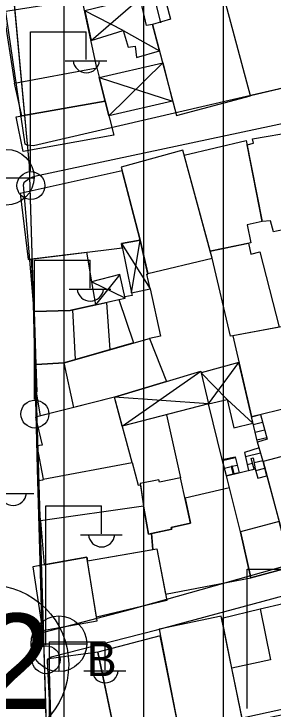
# Model space of a CAD drawing. Extents: x 417997 to 421451, y 4451742 to 4455216.
# Drawn here: x 419575.4 to 419608, y 4452787 to 4452874.4 of the extents above; entities that cross this region are included whole.
import ezdxf

# ---------------------------------------------------------------- set-up
doc = ezdxf.new("R2010")
doc.units = 0
for name, color, linetype in [('ADAKENARI', 7, 'Continuous'), ('B_Merdiven', 7, 'Continuous'), ('B_Mesken', 7, 'Continuous'), ('B_Sundurma', 7, 'Continuous'), ('B_Teras', 7, 'Continuous'), ('KD_DAIRE', 7, 'Continuous'), ('KD_YGEN', 7, 'Continuous'), ('PL_KON_MEV_350', 7, 'Continuous'), ('S_Elektrik_Diregi', 7, 'Continuous'), ('S_Rogar_Kapagi', 7, 'Continuous'), ('S_Rogar_Kapagi_Buski', 7, 'Continuous'), ('Sinir_Duvar_tek_tarafa_ait', 7, 'Continuous'), ('TR_ORTAYOGUNKONUT', 7, 'Continuous'), ('Yol_Sose', 7, 'Continuous')]:
    doc.layers.add(name, color=color, linetype=linetype)

msp = doc.modelspace()

# ---------------------------------------------------------------- linework, layer by layer
at = {"layer": 'ADAKENARI'}
for p, q in [((419577.387, 4452855.396), (419570.344, 4452931.114)), ((419577.387, 4452855.396), (419570.344, 4452931.114)), ((419580.562, 4452749.662), (419577.387, 4452855.396)), ((419580.562, 4452749.662), (419577.387, 4452855.396))]:
    msp.add_line(p, q, dxfattribs=at)
at = {"layer": 'B_Merdiven'}
for p, q in [((419605.259, 4452823.799), (419606.393, 4452824.078)), ((419605.49, 4452822.826), (419606.654, 4452823.113)), ((419605.72, 4452821.853), (419606.914, 4452822.147)), ((419605.95, 4452820.88), (419607.175, 4452821.181)), ((419604.497, 4452818.778), (419606.4, 4452819.269)), ((419601.631, 4452818.304), (419603.22, 4452818.69)), ((419604.723, 4452817.803), (419605.384, 4452817.974)), ((419605.599, 4452818.029), (419606.678, 4452818.308)), ((419601.877, 4452817.334), (419602.701, 4452817.535)), ((419602.84, 4452817.568), (419603.476, 4452817.723)), ((419605.795, 4452817.047), (419606.94, 4452817.343))]:
    msp.add_line(p, q, dxfattribs=at)
for points in [[(419606.391, 4452824.088), (419607.227, 4452820.991), (419606.016, 4452820.602), (419605.257, 4452823.808)], [(419607.199, 4452816.377), (419606.725, 4452818.149), (419606.218, 4452819.897), (419604.376, 4452819.299), (419604.899, 4452817.039), (419605.596, 4452817.209), (419605.223, 4452818.55), (419605.495, 4452818.609), (419605.74, 4452817.244), (419606.067, 4452816.085)], [(419602.124, 4452816.365), (419601.603, 4452818.415), (419603.202, 4452818.757), (419603.733, 4452816.756), (419603.101, 4452816.603), (419602.833, 4452817.597), (419602.697, 4452817.552), (419602.958, 4452816.568)]]:
    msp.add_lwpolyline(points, close=True, dxfattribs=at)
at = {"layer": 'B_Mesken'}
for points in [[(419601.122, 4452879.173), (419610.231, 4452881.446), (419611.357, 4452877.326), (419613.838, 4452866.195), (419605.127, 4452864.146)], [(419594.183, 4452877.313), (419595.097, 4452873.79), (419592.855, 4452873.132), (419595.839, 4452861.659), (419605.127, 4452864.146), (419601.122, 4452879.173)], [(419574.14, 4452874.723), (419575.523, 4452865.729), (419585.859, 4452867.663), (419584.005, 4452876.294)], [(419576.409, 4452861.628), (419575.523, 4452865.729), (419585.859, 4452867.663), (419586.893, 4452863.481)], [(419575.71, 4452861.505), (419586.893, 4452863.481), (419587.978, 4452859.205), (419576.599, 4452857.154)], [(419604.708, 4452857.963), (419605.529, 4452858.181), (419605.412, 4452858.754), (419610.784, 4452859.653), (419611.671, 4452855.297), (419612.25, 4452852.46), (419612.932, 4452849.113), (419613.116, 4452848.103), (419608.414, 4452847.12), (419608.031, 4452847.024), (419607.67, 4452848.42), (419606.623, 4452848.348)], [(419596.828, 4452856.671), (419604.594, 4452858.534), (419606.623, 4452848.348), (419604.737, 4452847.921), (419605.206, 4452845.68), (419600.086, 4452844.601)], [(419588.902, 4452855.173), (419591.287, 4452845.979), (419592.244, 4452841.79), (419600.323, 4452843.723), (419596.653, 4452857.32)], [(419589.017, 4452854.73), (419576.206, 4452851.873), (419577.234, 4452843.585), (419589.04, 4452845.013), (419588.927, 4452845.567), (419591.287, 4452845.979)], [(419602.924, 4452833.961), (419602.652, 4452833.916), (419600.323, 4452843.723), (419600.086, 4452844.601), (419604.898, 4452845.615), (419605.206, 4452844.251), (419606.326, 4452844.539), (419608.736, 4452835.055)], [(419578, 4452837.03), (419577.65, 4452843.636), (419584.53, 4452844.468), (419585.174, 4452840.763), (419585.696, 4452837.867), (419582.825, 4452837.219), (419582.477, 4452837.14)], [(419578.219, 4452830.344), (419578, 4452837.03), (419582.477, 4452837.14), (419588.616, 4452838.526), (419590.441, 4452833.069), (419581.74, 4452830.577)], [(419602.924, 4452833.961), (419605.257, 4452823.808), (419610.099, 4452825.001), (419610.158, 4452824.534), (419613.16, 4452825.235), (419610.827, 4452835.448)], [(419578.785, 4452823.922), (419578.253, 4452826.901), (419578.358, 4452826.945), (419578.219, 4452830.344), (419581.74, 4452830.577), (419592.468, 4452833.649), (419594.603, 4452828.231), (419588.043, 4452826.237), (419582.956, 4452824.965)], [(419579.115, 4452815.96), (419590.292, 4452818.025), (419588.043, 4452826.237), (419578.146, 4452823.762), (419578.994, 4452820.237), (419578.3, 4452820.133)], [(419606.725, 4452818.149), (419610.094, 4452805.561), (419617.6, 4452807.735), (419614.17, 4452820.157)], [(419590.292, 4452818.025), (419591.052, 4452815.191), (419591.315, 4452815.23), (419591.706, 4452812.571), (419578.778, 4452810.725), (419578.493, 4452815.773), (419579.115, 4452815.854), (419579.115, 4452815.96)], [(419603.877, 4452809.337), (419602.124, 4452816.365), (419605.74, 4452817.244), (419606.067, 4452816.085), (419607.199, 4452816.377), (419608.744, 4452810.604), (419610.094, 4452805.561), (419610.291, 4452804.915), (419605.198, 4452803.559)], [(419592.353, 4452809.035), (419595.279, 4452809.661), (419595.175, 4452809.872), (419597.618, 4452810.393), (419596.371, 4452816.133), (419593.716, 4452815.567), (419593.642, 4452815.853), (419591.289, 4452815.407), (419591.706, 4452812.571)], [(419602.499, 4452814.862), (419596.933, 4452813.548), (419597.618, 4452810.393), (419595.175, 4452809.872), (419595.279, 4452809.661), (419592.695, 4452809.108), (419592.863, 4452807.115), (419593.362, 4452807.203), (419594.458, 4452801.494), (419605.198, 4452803.559), (419603.877, 4452809.337)], [(419592.863, 4452807.115), (419592.695, 4452809.108), (419592.353, 4452809.035), (419591.706, 4452812.571), (419578.778, 4452810.725), (419579.23, 4452805.188), (419584.6, 4452806.15), (419584.677, 4452805.667)], [(419584.677, 4452805.667), (419593.362, 4452807.203), (419594.615, 4452800.672), (419585.814, 4452798.602)], [(419577.799, 4452804.932), (419579.004, 4452796.909), (419585.887, 4452798.151), (419584.6, 4452806.15)], [(419619.676, 4452789.297), (419604.107, 4452785.912), (419602.819, 4452792.194), (419601.535, 4452798.457), (419606.375, 4452799.656), (419609.266, 4452800.32), (419610.626, 4452793.413), (419618.507, 4452795.172)], [(419593.654, 4452797.091), (419596.33, 4452783.508), (419604.243, 4452785.245), (419601.477, 4452798.738)], [(419588.351, 4452782.743), (419596.17, 4452784.323), (419593.816, 4452796.267), (419585.978, 4452794.212)], [(419579.826, 4452793.341), (419580.148, 4452781.612), (419588.419, 4452782.417), (419585.978, 4452794.212)]]:
    msp.add_lwpolyline(points, close=True, dxfattribs=at)
at = {"layer": 'B_Sundurma'}
for p, q in [((419585.122, 4452871.095), (419591.306, 4452876.469)), ((419589.156, 4452872.349), (419584.319, 4452874.833)), ((419589.156, 4452872.349), (419593.718, 4452869.811)), ((419594.113, 4452868.293), (419587.357, 4452861.65)), ((419586.157, 4452866.458), (419595.367, 4452863.473)), ((419590.191, 4452839.374), (419591.287, 4452845.979)), ((419588.927, 4452845.567), (419592.551, 4452839.882)), ((419588.747, 4452841.666), (419585.696, 4452837.867)), ((419589.402, 4452838.705), (419585.174, 4452840.763)), ((419599.857, 4452825.413), (419603.695, 4452830.608)), ((419589.038, 4452822.604), (419598.885, 4452829.519)), ((419598.934, 4452829.307), (419602.23, 4452825.981)), ((419599.857, 4452825.413), (419588.043, 4452826.237)), ((419602.23, 4452825.981), (419605.456, 4452822.967))]:
    msp.add_line(p, q, dxfattribs=at)
for points in [[(419585.122, 4452871.095), (419589.156, 4452872.349), (419589.767, 4452870.264), (419590.641, 4452870.399), (419590.839, 4452868.98), (419593.718, 4452869.811), (419592.855, 4452873.132), (419592.061, 4452872.967), (419591.306, 4452876.469), (419590.759, 4452876.405), (419584.319, 4452874.833)], [(419586.157, 4452866.458), (419594.113, 4452868.293), (419595.367, 4452863.473), (419587.357, 4452861.65), (419586.893, 4452863.481)], [(419588.927, 4452845.567), (419590.191, 4452839.374), (419592.551, 4452839.882), (419592.136, 4452841.733), (419592.257, 4452841.733), (419592.257, 4452841.733), (419591.287, 4452845.979)], [(419588.616, 4452838.526), (419589.402, 4452838.705), (419588.747, 4452841.666), (419585.174, 4452840.763), (419585.696, 4452837.867), (419588.616, 4452838.526)], [(419603.695, 4452830.608), (419598.934, 4452829.307), (419599.857, 4452825.413), (419602.23, 4452825.981), (419603.033, 4452822.404), (419605.456, 4452822.967), (419605.257, 4452823.808), (419604.385, 4452827.602)], [(419599.857, 4452825.413), (419589.038, 4452822.604), (419588.043, 4452826.237), (419594.603, 4452828.231), (419598.885, 4452829.519), (419598.934, 4452829.307)]]:
    msp.add_lwpolyline(points, close=True, dxfattribs=at)
at = {"layer": 'B_Teras'}
for points in [[(419583.171, 4452830.987), (419582.825, 4452837.219), (419587.068, 4452838.176), (419587.474, 4452832.219)], [(419582.956, 4452824.965), (419581.74, 4452830.577), (419592.468, 4452833.649), (419594.603, 4452828.231), (419588.043, 4452826.237)], [(419608.744, 4452810.604), (419603.877, 4452809.337), (419605.198, 4452803.559), (419610.291, 4452804.915), (419610.094, 4452805.561)], [(419601.535, 4452798.457), (419606.375, 4452799.656), (419607.657, 4452793.212), (419602.819, 4452792.194)]]:
    msp.add_lwpolyline(points, close=True, dxfattribs=at)
at = {"layer": 'KD_DAIRE'}
msp.add_circle((419572.311, 4452792.652), 10, dxfattribs=at)
msp.add_circle((419572.311, 4452792.652), 10, dxfattribs=at)
at = {"layer": 'PL_KON_MEV_350'}
msp.add_lwpolyline([(419796.331, 4452996.105), (419805.412, 4452988.482), (419786.294, 4452689.029), (419775.978, 4452676.538), (419568.876, 4452622.815), (419561.752, 4452629.972), (419581.871, 4452706.077), (419635.792, 4452719.454), (419637.405, 4452760.32), (419700.317, 4452851.73), (419754.087, 4452844.74), (419741.182, 4452876.464), (419703.543, 4452885.605), (419700.317, 4452851.73), (419637.405, 4452760.32), (419580.562, 4452749.662), (419577.387, 4452855.396), (419570.344, 4452931.114), (419579.136, 4452943.428)], close=True, dxfattribs=at)
at = {"layer": 'S_Elektrik_Diregi'}
for p, q in [((419577.525, 4452854.699), (419577.525, 4452872.199)), ((419577.525, 4452872.199), (419584.525, 4452872.199)), ((419584.525, 4452868.699), (419584.525, 4452872.199)), ((419581.865, 4452868.559), (419587.115, 4452868.559)), ((419578.022, 4452825.965), (419578.022, 4452843.465)), ((419578.022, 4452843.465), (419585.022, 4452843.465)), ((419585.022, 4452839.965), (419585.022, 4452843.465)), ((419582.362, 4452839.825), (419587.612, 4452839.825)), ((419572.677, 4452814.146), (419577.927, 4452814.146)), ((419579.44, 4452795.073), (419579.44, 4452812.573)), ((419579.44, 4452812.573), (419586.44, 4452812.573)), ((419586.44, 4452809.073), (419586.44, 4452812.573)), ((419583.78, 4452808.933), (419589.03, 4452808.933)), ((419604.743, 4452787.119), (419604.743, 4452804.619)), ((419604.743, 4452804.619), (419611.743, 4452804.619)), ((419579.888, 4452777.982), (419579.888, 4452795.483)), ((419579.888, 4452795.483), (419586.888, 4452795.483)), ((419586.888, 4452791.982), (419586.888, 4452795.483)), ((419584.228, 4452791.842), (419589.478, 4452791.842))]:
    msp.add_line(p, q, dxfattribs=at)
for centre in [(419577.561, 4452852.863), (419578.058, 4452824.129), (419579.476, 4452793.237)]:
    msp.add_circle(centre, 1.75, dxfattribs=at)
for centre in [(419584.526, 4452868.712), (419585.023, 4452839.978), (419575.338, 4452814.299), (419586.441, 4452809.086), (419586.889, 4452791.995)]:
    msp.add_arc(centre, 1.658, 184.83843, 355.14641, dxfattribs=at)
at = {"layer": 'S_Rogar_Kapagi'}
msp.add_line((419570.954, 4452853.844), (419577.954, 4452853.844), dxfattribs=at)
msp.add_circle((419574.47, 4452853.908), 3.5, dxfattribs=at)
at = {"layer": 'S_Rogar_Kapagi_Buski'}
for p, q in [((419581.084, 4452798.745), (419581.084, 4452791.745)), ((419577.584, 4452795.245), (419584.584, 4452795.245))]:
    msp.add_line(p, q, dxfattribs=at)
msp.add_circle((419581.084, 4452795.245), 3.5, dxfattribs=at)
at = {"layer": 'Sinir_Duvar_tek_tarafa_ait'}
for points in [[(419593.883, 4452873.308), (419591.839, 4452881.71), (419598.45, 4452883.448)], [(419592.551, 4452839.882), (419593.831, 4452833.944), (419592.468, 4452833.649)], [(419590.191, 4452839.374), (419590.266, 4452839.057), (419589.361, 4452838.89)], [(419601.603, 4452818.415), (419599.857, 4452825.413)], [(419594.605, 4452824.05), (419596.371, 4452816.133)], [(419606.218, 4452819.897), (419606.016, 4452820.602)]]:
    msp.add_lwpolyline(points, dxfattribs=at)
at = {"layer": 'TR_ORTAYOGUNKONUT'}
for p, q in [((419601.752, 4452753.635), (419601.752, 4452948.913)), ((419601.752, 4452753.635), (419601.752, 4452948.913)), ((419591.752, 4452751.76), (419591.752, 4452946.488)), ((419591.752, 4452751.76), (419591.752, 4452946.488)), ((419581.752, 4452749.885), (419581.752, 4452944.063)), ((419581.752, 4452749.885), (419581.752, 4452944.063))]:
    msp.add_line(p, q, dxfattribs=at)
at = {"layer": 'Yol_Sose'}
for points in [[(419649.092, 4452874.82), (419614.412, 4452866.344), (419577.883, 4452857.842), (419577.095, 4452857.935), (419576.838, 4452858.087), (419570.897, 4452898.516), (419571.02, 4452899.046), (419571.157, 4452899.379), (419571.628, 4452899.832), (419571.765, 4452899.937), (419603.408, 4452915.053), (419632.609, 4452929.22), (419634.096, 4452929.823), (419671.372, 4452939.159), (419686.352, 4452942.891)], [(419614.076, 4452806.318), (419589.992, 4452799.515), (419579.301, 4452796.708), (419579.134, 4452796.708), (419578.968, 4452796.875), (419578.384, 4452817.243), (419577.908, 4452838.02), (419576.654, 4452852.942), (419576.701, 4452853.245), (419576.731, 4452853.29), (419577.354, 4452853.743), (419578.022, 4452854.044), (419610.075, 4452860.876)], [(419670.465, 4452799.794), (419649.067, 4452794.861), (419619.795, 4452788.511), (419588.117, 4452781.942), (419580.594, 4452781.341), (419580.398, 4452781.402), (419580.292, 4452781.553), (419580.248, 4452781.735), (419579.665, 4452793.069), (419579.665, 4452793.235), (419579.726, 4452793.371), (419580.121, 4452793.612), (419593.373, 4452797.009), (419610.457, 4452801.621), (419650.818, 4452812.022), (419663.965, 4452815.525), (419664.525, 4452815.781), (419664.738, 4452816.007), (419664.799, 4452816.113), (419666.555, 4452820.792), (419668.556, 4452844.693)]]:
    msp.add_lwpolyline(points, dxfattribs=at)

# ---------------------------------------------------------------- texts
at = {"layer": 'KD_YGEN'}
msp.add_text('12', height=12, dxfattribs=at).set_placement((419562.336, 4452787.037))
msp.add_text('12', height=12, dxfattribs=at).set_placement((419562.336, 4452787.037))
at = {"layer": 'S_Rogar_Kapagi_Buski'}
msp.add_text('B', height=4.2, dxfattribs=at).set_placement((419584.584, 4452791.18))

doc.saveas('drawing.dxf')
